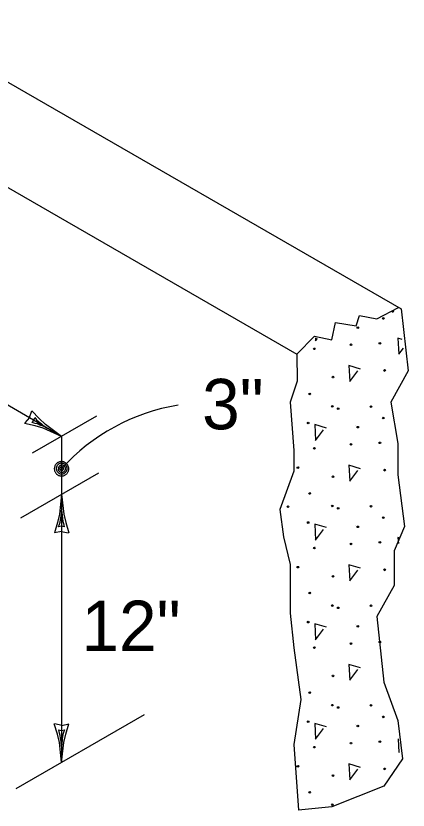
# Model space of a CAD drawing. Extents: x -7.1 to 10, y -5 to 6.
# Drawn here: x 3.657 to 4.17, y 3.533 to 4.574 of the extents above; entities that cross this region are included whole.
import ezdxf

# ---------------------------------------------------------------- set-up
doc = ezdxf.new("R2010")
doc.units = 0
for name, color, linetype in [('Level 4', 7, 'Continuous'), ('Level 5', 7, 'Continuous'), ('Level 6', 7, 'Continuous'), ('Level 7', 7, 'Continuous')]:
    doc.layers.add(name, color=color, linetype=linetype)

msp = doc.modelspace()

# ---------------------------------------------------------------- linework, layer by layer
at = {"layer": 'Level 4'}
for p, q in [((3.4958, 4.5737), (4.161, 4.1897)), ((3.5265, 4.4179), (4.0246, 4.1304))]:
    msp.add_line(p, q, dxfattribs=at)
for points in [[(4.0246, 4.1304), (4.0478, 4.1537), (4.0705, 4.1492), (4.075, 4.1719), (4.1022, 4.1673), (4.1067, 4.1809), (4.1294, 4.1764), (4.1576, 4.1916)], [(4.161, 4.1897), (4.1702, 4.1084), (4.1476, 4.0676), (4.1566, 4.0131), (4.1566, 3.9723), (4.1657, 3.9043), (4.1521, 3.8725), (4.1521, 3.8272), (4.1294, 3.7863), (4.1385, 3.7002), (4.1566, 3.6503), (4.163, 3.5997)], [(4.0246, 4.1304), (4.0251, 4.0948), (4.016, 4.0676), (4.0206, 4.0041), (4.0206, 3.9768), (4.0024, 3.9269), (4.007, 3.8907), (4.016, 3.8544), (4.016, 3.7909), (4.0206, 3.7455), (4.0296, 3.6775), (4.0206, 3.6185), (4.0266, 3.5327)], [(4.163, 3.5997), (4.1385, 3.5641), (4.0705, 3.5369), (4.0266, 3.5327)]]:
    msp.add_lwpolyline(points, dxfattribs=at)
at = {"layer": 'Level 5'}
for p, q in [((4.1012, 4.1672), (4.1014, 4.1672)), ((4.049, 4.1517), (4.0492, 4.1476)), ((4.0492, 4.1476), (4.0517, 4.1509)), ((4.1626, 4.1496), (4.157, 4.1513)), ((4.157, 4.1513), (4.1582, 4.1303)), ((4.0494, 4.1387), (4.0494, 4.1387)), ((4.1582, 4.1303), (4.1642, 4.1383)), ((4.1385, 4.109), (4.1385, 4.109)), ((4.1385, 4.109), (4.1392, 4.1075)), ((4.0717, 4.1003), (4.0716, 4.099)), ((4.042, 4.0793), (4.0424, 4.0779)), ((4.0804, 4.059), (4.0804, 4.059)), ((4.1012, 4.0366), (4.1014, 4.0367)), ((4.0494, 4.0082), (4.0494, 4.0082)), ((4.0276, 3.9822), (4.0262, 3.9813)), ((4.0276, 3.9822), (4.0276, 3.9822)), ((4.1385, 3.9785), (4.1385, 3.9785)), ((4.1385, 3.9785), (4.1392, 3.9769)), ((4.0717, 3.9698), (4.0716, 3.9685)), ((4.042, 3.9488), (4.0424, 3.9474)), ((4.0029, 3.9247), (4.0029, 3.9247)), ((4.0128, 3.9302), (4.0128, 3.9302)), ((4.0804, 3.9284), (4.0804, 3.9284)), ((4.1012, 3.9061), (4.1014, 3.9061)), ((4.1598, 3.8893), (4.157, 3.8902)), ((4.157, 3.8902), (4.1575, 3.8822)), ((4.0494, 3.8777), (4.0494, 3.8777)), ((4.0276, 3.8517), (4.0262, 3.8508)), ((4.0276, 3.8517), (4.0276, 3.8517)), ((4.1385, 3.8479), (4.1385, 3.8479)), ((4.1385, 3.8479), (4.1392, 3.8464)), ((4.0717, 3.8393), (4.0716, 3.8379)), ((4.042, 3.8182), (4.0424, 3.8169)), ((4.0804, 3.7979), (4.0804, 3.7979)), ((4.1012, 3.7756), (4.1014, 3.7756)), ((4.0494, 3.7471), (4.0494, 3.7471)), ((4.0276, 3.7211), (4.0276, 3.7211)), ((4.0276, 3.7211), (4.0276, 3.7211)), ((4.0717, 3.7087), (4.0716, 3.7074)), ((4.042, 3.6877), (4.0424, 3.6863)), ((4.0804, 3.6673), (4.0804, 3.6673)), ((4.1012, 3.645), (4.1014, 3.6451)), ((4.1572, 3.626), (4.1582, 3.6081)), ((4.0494, 3.6166), (4.0494, 3.6166)), ((4.1582, 3.6081), (4.1586, 3.6088)), ((4.0276, 3.5906), (4.0262, 3.5897)), ((4.0276, 3.5906), (4.0276, 3.5906)), ((4.1385, 3.5869), (4.1385, 3.5869)), ((4.1385, 3.5869), (4.1392, 3.5853)), ((4.0717, 3.5782), (4.0716, 3.5768)), ((4.042, 3.5571), (4.0424, 3.5558))]:
    msp.add_line(p, q, dxfattribs=at)
for points in [[(4.1078, 4.1107), (4.0926, 4.1154), (4.0938, 4.0944), (4.1043, 4.1084)], [(4.0632, 4.0334), (4.048, 4.0381), (4.0492, 4.0171), (4.0597, 4.0311)], [(4.1078, 3.9802), (4.0926, 3.9848), (4.0938, 3.9639), (4.1043, 3.9778)], [(4.0632, 3.9029), (4.048, 3.9075), (4.0492, 3.8866), (4.0597, 3.9005)], [(4.1078, 3.8496), (4.0926, 3.8543), (4.0938, 3.8333), (4.1043, 3.8473)], [(4.0632, 3.7723), (4.048, 3.777), (4.0492, 3.756), (4.0597, 3.77)], [(4.1078, 3.7191), (4.0926, 3.7237), (4.0938, 3.7028), (4.1043, 3.7168)], [(4.0632, 3.6418), (4.048, 3.6464), (4.0492, 3.6255), (4.0597, 3.6395)], [(4.1078, 3.5885), (4.0926, 3.5932), (4.0938, 3.5722), (4.1043, 3.5862)]]:
    msp.add_lwpolyline(points, dxfattribs=at)
for centre in [(4.15, 4.1862), (4.1377, 4.1771), (4.1044, 4.1651), (4.0956, 4.1426), (4.1333, 4.1446), (4.0476, 4.1373), (4.1395, 4.109), (4.0719, 4.1002), (4.0415, 4.0782), (4.071, 4.0619), (4.1217, 4.0616), (4.0787, 4.0589), (4.0394, 4.0401), (4.1377, 4.0466), (4.1044, 4.0346), (4.0956, 4.012), (4.1333, 4.0141), (4.0476, 4.0068), (4.0259, 3.9816), (4.1395, 3.9784), (4.0719, 3.9696), (4.0415, 3.9477), (4.0131, 3.9304), (4.071, 3.9313), (4.0787, 3.9283), (4.1217, 3.931), (4.1377, 3.916), (4.0394, 3.9096), (4.1044, 3.904), (4.1333, 3.8836), (4.0476, 3.8762), (4.0956, 3.8815), (4.0259, 3.8511), (4.1395, 3.8479), (4.0719, 3.8391), (4.0415, 3.8172), (4.071, 3.8008), (4.1217, 3.8005), (4.0787, 3.7978), (4.0394, 3.7791), (4.1044, 3.7735), (4.0956, 3.751), (4.1333, 3.753), (4.0476, 3.7457), (4.0719, 3.7086), (4.0415, 3.6866), (4.071, 3.6702), (4.0787, 3.6672), (4.1217, 3.6699), (4.1377, 3.6549), (4.0394, 3.6485), (4.1044, 3.643), (4.1333, 3.6225), (4.0476, 3.6152), (4.0956, 3.6204), (4.0259, 3.59), (4.1395, 3.5868), (4.0719, 3.578), (4.0415, 3.5561), (4.071, 3.5397)]:
    msp.add_circle(centre, 0.00105, dxfattribs=at)
at = {"layer": 'Level 7'}
for p, q in [((3.7166, 4.0226), (3.5435, 4.1226)), ((3.6746, 4.0471), (3.6776, 4.0559)), ((3.6746, 4.0471), (3.6685, 4.0402)), ((3.6787, 4.0008), (3.7629, 4.0494)), ((3.7166, 4.0226), (3.7166, 3.9466)), ((3.6632, 3.9158), (3.7653, 3.9747)), ((3.7166, 3.9466), (3.7166, 3.5952)), ((3.7164, 3.898), (3.7073, 3.8962)), ((3.7164, 3.898), (3.7254, 3.8962)), ((3.6572, 3.5609), (3.8251, 3.6579)), ((3.7168, 3.6438), (3.7077, 3.6456)), ((3.7168, 3.6438), (3.7259, 3.6456))]:
    msp.add_line(p, q, dxfattribs=at)
for points in [[(3.7166, 4.0226), (3.6955, 4.038), (3.6874, 4.0458), (3.6776, 4.0559)], [(3.7166, 4.0226), (3.6927, 4.0331), (3.6819, 4.0363), (3.6681, 4.0396)], [(3.6987, 4.033), (3.6924, 4.0359), (3.6883, 4.0373), (3.685, 4.0388), (3.6821, 4.0395), (3.6779, 4.0407), (3.6804, 4.0435), (3.6817, 4.0472), (3.684, 4.0443), (3.6859, 4.0424), (3.6882, 4.0407), (3.6902, 4.0389), (3.6922, 4.0374), (3.6944, 4.0357), (3.6987, 4.033)], [(3.7166, 3.9466), (3.7138, 3.9207), (3.7111, 3.9097), (3.7073, 3.8962)], [(3.7166, 3.9466), (3.7194, 3.9207), (3.7221, 3.9097), (3.7261, 3.8961)], [(3.7166, 3.9259), (3.7172, 3.9191), (3.718, 3.9148), (3.7184, 3.9111), (3.7192, 3.9083), (3.7202, 3.904), (3.7166, 3.9049), (3.7127, 3.9041), (3.7141, 3.9075), (3.7148, 3.9101), (3.7152, 3.913), (3.7158, 3.9156), (3.716, 3.918), (3.7164, 3.9209), (3.7166, 3.9259)], [(3.7166, 3.5952), (3.7137, 3.6211), (3.7111, 3.6321), (3.7071, 3.6456)], [(3.7166, 3.5952), (3.7194, 3.6211), (3.7221, 3.6321), (3.7259, 3.6456)], [(3.7166, 3.6159), (3.716, 3.6227), (3.7152, 3.627), (3.7148, 3.6306), (3.7139, 3.6335), (3.7129, 3.6378), (3.7166, 3.6369), (3.7204, 3.6377), (3.719, 3.6343), (3.7184, 3.6317), (3.718, 3.6288), (3.7174, 3.6262), (3.7172, 3.6238), (3.7168, 3.6209), (3.7166, 3.6159)]]:
    msp.add_lwpolyline(points, dxfattribs=at)
for points in [[(3.7101, 3.9732), (3.7107, 3.9727), (3.7114, 3.9722), (3.7121, 3.9718), (3.7128, 3.9714), (3.7136, 3.9711), (3.7144, 3.9709), (3.7152, 3.9708), (3.716, 3.9707), (3.7168, 3.9707), (3.7177, 3.9707), (3.7185, 3.9708), (3.7193, 3.971), (3.7201, 3.9713), (3.7208, 3.9717), (3.7215, 3.9721), (3.7222, 3.9725), (3.7228, 3.973), (3.7234, 3.9736), (3.724, 3.9742), (3.7244, 3.9749), (3.7249, 3.9756), (3.7252, 3.9763), (3.7255, 3.9771), (3.7257, 3.9779), (3.7259, 3.9787), (3.726, 3.9795), (3.726, 3.9804), (3.7259, 3.9812), (3.7258, 3.982), (3.7256, 3.9828), (3.7253, 3.9836), (3.725, 3.9843), (3.7246, 3.985), (3.7241, 3.9857), (3.7236, 3.9864), (3.723, 3.9869), (3.7224, 3.9875), (3.7218, 3.988), (3.721, 3.9884), (3.7203, 3.9888), (3.7195, 3.989), (3.7187, 3.9893), (3.7179, 3.9894), (3.7171, 3.9895), (3.7163, 3.9895), (3.7155, 3.9895), (3.7147, 3.9893), (3.7139, 3.9891), (3.7131, 3.9889), (3.7123, 3.9885), (3.7116, 3.9881), (3.7109, 3.9877), (3.7103, 3.9871), (3.7097, 3.9866), (3.7092, 3.9859), (3.7087, 3.9853), (3.7083, 3.9846), (3.7079, 3.9838), (3.7076, 3.9831), (3.7074, 3.9823), (3.7072, 3.9814), (3.7071, 3.9806), (3.7071, 3.9798), (3.7072, 3.979), (3.7073, 3.9782), (3.7075, 3.9774), (3.7078, 3.9766), (3.7081, 3.9759), (3.7085, 3.9751), (3.709, 3.9744), (3.7095, 3.9738)], [(3.7119, 3.9752), (3.7124, 3.9748), (3.7129, 3.9744), (3.7134, 3.9741), (3.714, 3.9738), (3.7146, 3.9736), (3.7152, 3.9735), (3.7158, 3.9733), (3.7164, 3.9733), (3.717, 3.9733), (3.7176, 3.9733), (3.7182, 3.9734), (3.7188, 3.9736), (3.7194, 3.9738), (3.72, 3.974), (3.7205, 3.9743), (3.721, 3.9747), (3.7215, 3.9751), (3.722, 3.9755), (3.7224, 3.9759), (3.7227, 3.9764), (3.723, 3.977), (3.7233, 3.9775), (3.7235, 3.9781), (3.7237, 3.9787), (3.7238, 3.9793), (3.7239, 3.9799), (3.7239, 3.9805), (3.7238, 3.9812), (3.7237, 3.9818), (3.7236, 3.9824), (3.7234, 3.9829), (3.7231, 3.9835), (3.7228, 3.9841), (3.7225, 3.9846), (3.7221, 3.985), (3.7217, 3.9855), (3.7212, 3.9859), (3.7207, 3.9863), (3.7202, 3.9866), (3.7196, 3.9868), (3.719, 3.9871), (3.7184, 3.9872), (3.7178, 3.9873), (3.7172, 3.9874), (3.7166, 3.9874), (3.716, 3.9874), (3.7154, 3.9873), (3.7148, 3.9871), (3.7142, 3.9869), (3.7136, 3.9867), (3.7131, 3.9864), (3.7126, 3.986), (3.7121, 3.9856), (3.7117, 3.9852), (3.7113, 3.9847), (3.7109, 3.9842), (3.7106, 3.9837), (3.7103, 3.9831), (3.7101, 3.9826), (3.7099, 3.982), (3.7098, 3.9814), (3.7097, 3.9808), (3.7097, 3.9801), (3.7098, 3.9795), (3.7099, 3.9789), (3.71, 3.9783), (3.7102, 3.9777), (3.7105, 3.9772), (3.7108, 3.9766), (3.7111, 3.9761), (3.7115, 3.9756)], [(3.7138, 3.9767), (3.7141, 3.9764), (3.7145, 3.9762), (3.7148, 3.9759), (3.7152, 3.9758), (3.7156, 3.9756), (3.716, 3.9755), (3.7164, 3.9754), (3.7168, 3.9754), (3.7172, 3.9754), (3.7176, 3.9754), (3.718, 3.9755), (3.7184, 3.9756), (3.7188, 3.9757), (3.7192, 3.9759), (3.7195, 3.9761), (3.7199, 3.9763), (3.7202, 3.9766), (3.7205, 3.9769), (3.7208, 3.9772), (3.721, 3.9775), (3.7212, 3.9779), (3.7214, 3.9782), (3.7215, 3.9786), (3.7217, 3.979), (3.7217, 3.9794), (3.7218, 3.9798), (3.7218, 3.9802), (3.7218, 3.9806), (3.7217, 3.9811), (3.7216, 3.9814), (3.7214, 3.9818), (3.7213, 3.9822), (3.7211, 3.9826), (3.7208, 3.9829), (3.7206, 3.9832), (3.7203, 3.9835), (3.72, 3.9838), (3.7197, 3.984), (3.7193, 3.9843), (3.7189, 3.9844), (3.7186, 3.9846), (3.7182, 3.9847), (3.7178, 3.9848), (3.7173, 3.9848), (3.7169, 3.9848), (3.7165, 3.9848), (3.7161, 3.9847), (3.7157, 3.9846), (3.7153, 3.9845), (3.7149, 3.9843), (3.7146, 3.9841), (3.7143, 3.9839), (3.7139, 3.9836), (3.7136, 3.9833), (3.7134, 3.983), (3.7131, 3.9827), (3.7129, 3.9823), (3.7127, 3.982), (3.7126, 3.9816), (3.7125, 3.9812), (3.7124, 3.9808), (3.7124, 3.9804), (3.7123, 3.98), (3.7124, 3.9796), (3.7124, 3.9791), (3.7125, 3.9788), (3.7127, 3.9784), (3.7128, 3.978), (3.7131, 3.9776), (3.7133, 3.9773), (3.7135, 3.977)], [(3.7152, 3.9786), (3.7153, 3.9785), (3.7155, 3.9784), (3.7157, 3.9783), (3.7159, 3.9782), (3.7161, 3.9781), (3.7163, 3.978), (3.7165, 3.978), (3.7167, 3.978), (3.7169, 3.978), (3.7171, 3.978), (3.7173, 3.978), (3.7175, 3.9781), (3.7177, 3.9781), (3.7179, 3.9782), (3.718, 3.9783), (3.7182, 3.9784), (3.7184, 3.9786), (3.7185, 3.9787), (3.7187, 3.9789), (3.7188, 3.979), (3.7189, 3.9792), (3.719, 3.9794), (3.719, 3.9796), (3.7191, 3.9798), (3.7191, 3.98), (3.7192, 3.9802), (3.7192, 3.9804), (3.7191, 3.9806), (3.7191, 3.9808), (3.7191, 3.981), (3.719, 3.9812), (3.7189, 3.9814), (3.7188, 3.9816), (3.7187, 3.9818), (3.7186, 3.9819), (3.7184, 3.9821), (3.7183, 3.9822), (3.7181, 3.9823), (3.7179, 3.9824), (3.7177, 3.9825), (3.7176, 3.9826), (3.7174, 3.9826), (3.7171, 3.9827), (3.7169, 3.9827), (3.7167, 3.9827), (3.7165, 3.9827), (3.7163, 3.9826), (3.7161, 3.9826), (3.7159, 3.9825), (3.7158, 3.9824), (3.7156, 3.9823), (3.7154, 3.9822), (3.7152, 3.9821), (3.7151, 3.982), (3.715, 3.9818), (3.7148, 3.9816), (3.7147, 3.9815), (3.7146, 3.9813), (3.7146, 3.9811), (3.7145, 3.9809), (3.7145, 3.9807), (3.7144, 3.9805), (3.7144, 3.9803), (3.7145, 3.9801), (3.7145, 3.9799), (3.7146, 3.9797), (3.7146, 3.9795), (3.7147, 3.9793), (3.7148, 3.9791), (3.7149, 3.9789), (3.715, 3.9788)]]:
    msp.add_lwpolyline(points, close=True, dxfattribs=at)
msp.add_arc((3.9118, 3.804), 0.2629, 99.3202, 137.9516, dxfattribs=at)

# ---------------------------------------------------------------- texts
at = {"layer": 'Level 6'}
for s, p in [('3"', (3.9006, 4.0318)), ('12"', (3.7427, 3.7411))]:
    msp.add_text(s, height=0.06613, dxfattribs=at).set_placement(p)

doc.saveas('drawing.dxf')
